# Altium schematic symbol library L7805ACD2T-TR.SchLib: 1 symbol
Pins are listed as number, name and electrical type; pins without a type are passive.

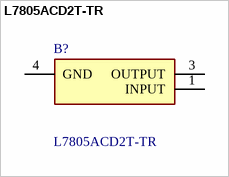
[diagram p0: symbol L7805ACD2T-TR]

## L7805ACD2T-TR
designator B?
Voltage Regulator 5V 1A D2PAK STMicroelectronics L78xx L7805ACD2T-TR, Single Linear Voltage Regulator, 1.5A 5 V, +/-2%, 3-Pin D2PAK
footprint D2PAK-STB35NF10T4
pins: 1 INPUT, 3 OUTPUT, 4 GND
